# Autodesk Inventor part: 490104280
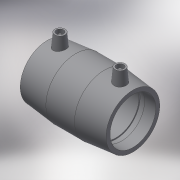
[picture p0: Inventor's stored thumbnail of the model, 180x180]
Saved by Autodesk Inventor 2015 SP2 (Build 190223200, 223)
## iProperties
Created: 2017-06
Part Number: 490104280
Material: Generic
Description: PLASSON COUPLER 280-280
Document SubType Name: Modeling
Designer: KIM
Mass: 6982.95 g
Surface Area: 5956.78 cm^2
Volume: 6982.95 cm^3
Density: 1 g/cm^3
Appearance: Default
Author: KIM
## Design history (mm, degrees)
derived "490104.ipt"
feature "Solid1::490104.ipt"
tag "TaggingFeature1"
body "Solid1"
other parameters: "d0" = 275, "d2" = 342, "d3" = 134, "d4" = 91.66667, "d5" = 307.8, "d6" = 266, "d8" = 168 deg, "d10" = 53.6, "d11" = 17.86667, "d13" = 275, "d14" = 17.6296, "d15" = 134, "d16" = 134, "d17" = 266, "d19" = 3.52592, "d20" = 168 deg, "d22" = 321.48, "d23" = 342, "d24" = 311.8356, "d25" = 135 deg, "d26" = 151.25, "d27" = 135 deg, "d30" = 14, "d31" = 96.25, "d34" = 5 deg, "d35" = 15, "d39" = 5 deg, "d41" = 4, "d42" = 14, "d43" = 0, "d45" = 4, "d46" = 14, "d47" = 0, "d48" = 3, "d49" = 0, "d50" = 3, "d51" = 0, "d52" = 38.86, "d53" = 9.715, "L_" = 275, "L_1" = 134, "D_" = 342, "d_2" = 12
